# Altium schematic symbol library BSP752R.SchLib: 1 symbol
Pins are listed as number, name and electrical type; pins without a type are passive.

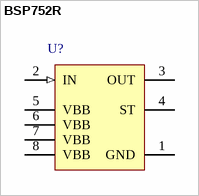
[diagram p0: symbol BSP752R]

## BSP752R
designator U?
Smart High-Side Power Switch, 1 Channel, 1.3 A Load Current, -40 to 150 degC, PG-DSO-8-24, Reel, Green; Manufacturer: Infineon; PartNumber: BSP752R; Channels: 1; Green: TRUE; Group: Automotive Qualified; Load Current (typ): 1.3 A; Ptot (max): 1.5 W; Recommended Operating Voltage Max.: 52 V; Recommended Operating Voltage Min.: 6 V; RON @ 25degreesC: 200 mOhm; RON(max) @ 150degreesC: 380 mOhm; toff (max): 200 us; ton (max): 180 us
footprint INF-PG-DSO-8-24_N (SOP, 8-Leads, Body 4.9x3.9mm, Pitch 1.27mm, IPC Medium Density)
footprint INF-PG-DSO-8-24_L (SOP, 8-Leads, Body 4.9x3.9mm, Pitch 1.27mm, IPC High Density)
footprint INF-PG-DSO-8-24_M (SOP, 8-Leads, Body 4.9x3.9mm, Pitch 1.27mm, IPC Low Density)
pins: 1 GND (power) "Logic ground", 2 IN (in) "Input, activates the power switch in case of logic high signal.", 3 OUT (power) "Output to the load.", 4 ST (oc) "Diagnostic feedback.", 5 VBB (power) "Positive power supply voltage.", 6 VBB (power) "Positive power supply voltage.", 7 VBB (power) "Positive power supply voltage.", 8 VBB (power) "Positive power supply voltage."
